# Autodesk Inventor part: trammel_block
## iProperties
Created: 2008-11
Part Number: trammel_block
Document SubType Name: Modeling
Designer: Lochan
Density: 1 g/cm^3
Author: Lochan
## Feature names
1. Extrusion1
2. Extrusion2
3. Extrusion3
